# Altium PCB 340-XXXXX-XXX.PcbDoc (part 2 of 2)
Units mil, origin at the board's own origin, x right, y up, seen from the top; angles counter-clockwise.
Board outline 2825 x 4480 mil, 2 copper layers (Top Layer, Bottom Layer), stack 60.8 mil thick; 87 components, 73 nets, 344 pads, 146 vias.
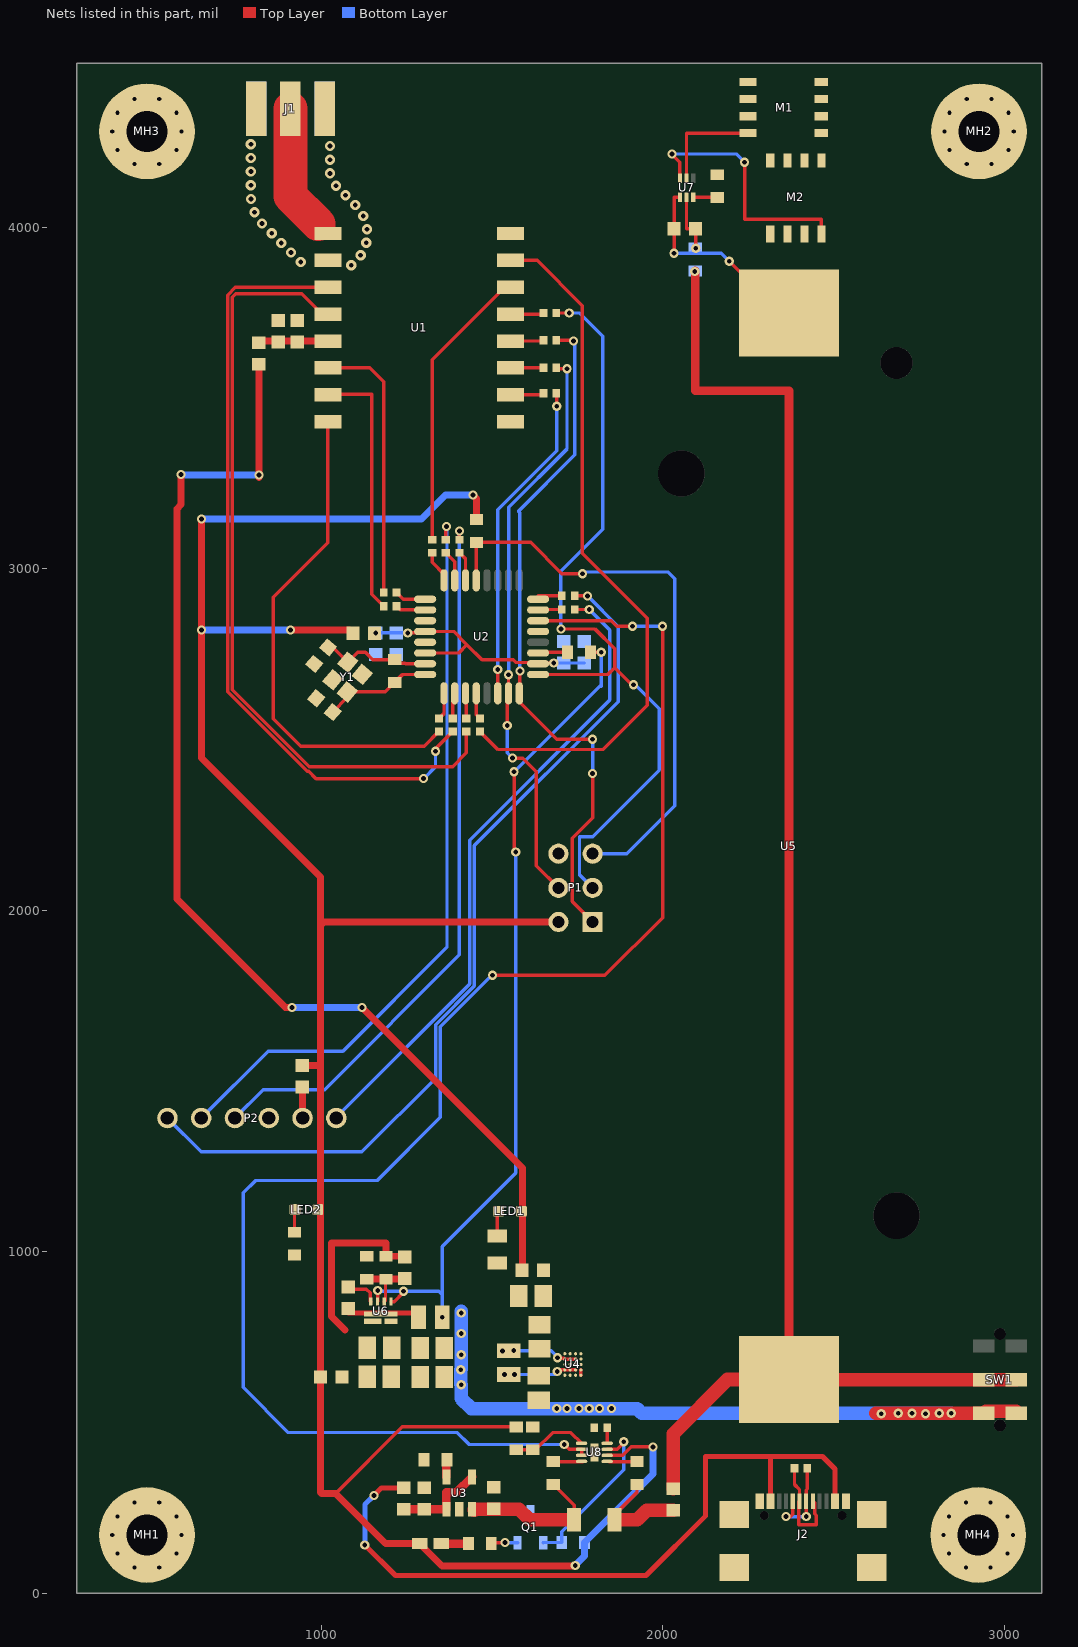
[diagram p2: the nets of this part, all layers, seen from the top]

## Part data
C1 C3 C4 C5: library part 060-00124-000, "CAP, CER, SMT, 25V, +/- 10%, X7R, 0603", DIELECTRIC=X7R, Manufacturer="Kemet Corporation", Manufacturer P/N=C0603C104K3RAC, Package=C0603, TOLERANCE=10%, Value (nF)=100, Value (pF)=100000, Value (µF)=0.1, Voltage=25V
C2 C3 C8 C9: library part 060-00192-001, "CAP, CER, SMT, 1.0UF, 25V, 10%, X5R, 0603", DIELECTRIC=X5R, Manufacturer="Kemet Corporation", Manufacturer P/N=C0603C105K3PAC, Package=C0603, TOLERANCE=10%, Value (nF)=1000, Value (pF)=1000000, Value (µF)=1, Voltage=25V
C6 C7: library part 060-00139-005, "CAP, CER, 10%, 50V, 27PF, CAP0603", DIELECTRIC=NP0, Manufacturer="Kemet Corporation", Manufacturer P/N=C0603C270K5GAC, Package=C0603, TOLERANCE=10%, Value (nF)=0.027, Value (pF)=27, Value (µF)=0.000027, Voltage=50V
C10 C11 C17 C18: library part 060-00196-000, "CAP, CER, 10UF, 16V, X5R, 0805", DIELECTRIC=X5R, Manufacturer="Murata Manufacturing Co., Ltd.", Manufacturer P/N=GRM21BR61C106KE15L, Package=C0805, TOLERANCE=10%, Value (nF)=10000, Value (pF)=10000000, Value (µF)=10, Voltage=16V
C12: library part 060-00269-000, "CAP, CER, 0805, 20%, 6.3V, X5R, 47UF", DIELECTRIC=X5R, Manufacturer="Kemet Corporation", Manufacturer P/N=C0805C476M9PACTU, Package=C0805, TOLERANCE=20%, Value (nF)=47000, Value (pF)=47000000, Value (µF)=47, Voltage=6.3V
C13: library part 060-00243-000, "CAP, CER, 5%, 25V, C0G, 0603, 10,000PF", DIELECTRIC=NP0, Manufacturer="TDK Corporation", Manufacturer P/N=C1608C0G1E103JT, Package=C0603, TOLERANCE=5%, Value (nF)=10, Value (pF)=10000, Value (µF)=0.01, Voltage=25V
C14 C15: library part 060-00268-000, "CAP, CER, 0805, 20%, 10V, X7R, 22UF", DIELECTRIC=X7R, Manufacturer="Taiyo Yuden USA, Inc.", Manufacturer P/N=LMK212BJ226MG-T, Package=C0805, TOLERANCE=20%, Value (nF)=22000, Value (pF)=22000000, Value (µF)=22, Voltage=10V
C16: library part 064-00028-016, "CAP RF, HIQ, NPO, +/-1%, 10GHZ, 200, 100V, 0603, 10PF, ROHS", DIELECTRIC=NP0, Manufacturer=Vishay, Manufacturer P/N=VJ0603D100FXBA, Package=C0603, TOLERANCE=1%, Value (nF)=0.01, Value (pF)=10, Value (µF)=0.00001, Voltage=100V
C19: library part 060-00041-000, "CAP, CER, SMT, 25V, +80/-20%,Y5V,0603,.1uf", DIELECTRIC=Y5V, Manufacturer="Kemet Corporation", Manufacturer P/N=C0603C104M3VAC, Package=C0603, TOLERANCE=20%, Value (nF)=100, Value (pF)=100000, Value (µF)=0.1, Voltage=25V
D1: library part 023-00316-000, "DIODE, LED, RED, SMT, 2.5V, 0603", Current=20mA, LED_COLOR=RED, Manufacturer=Kingbright, Package=D0603, Voltage=2.5V
FB1 FB2 FB3 FB4 FB5 FB6 FB7: library part 082-00014-004, "FERRITE,100MHZ,0603,25%,120OHM ROHS", Current=2A, Manufacturer=Murata, Package=L0603
J1: library part 030-00761-000, "CONN, SMA JACK, FEMALE, EDGE", Manufacturer=LINX, Package=SMA
J2: library part USB4110-GF-A, "CONN USB 2.0 TYPE-C R/A SMT", Manufacturer=GCT
L1 L2: library part 080-00223-000, "INDUCTOR POWER 1UH 1.5A SMD", Current=3.1A, Current_Sat=3.5A, Manufacturer="Vishay Dale", Manufacturer P/N=IHHP0806AZER1R0M01, Package="0.079\" L x 0.063\" W", TOLERANCE=20%
LED1 LED2: library part LED_SMD_Green_0603_570nm, "LED 0603 SMD Green 570nm 50mcd 20mA", Current - Test=20mA, Manufacturer 1="Kingbright Company LLC", Manufacturer Part Number 1=APT1608CGCK, Package / Case="0603 (1608 metric)", Ratings="20mcd min; 50 mcd typ; 570 nm", Supplier Part Number 1=754-1116-1-ND, Voltage - Forward (Vf) @ 10mA=2.0V, Voltage - Forward (Vf) Typ=2.1V
M1 M2: library part FDMS7692, "MOSFET N-CH 30V 14A POWER56", Manufacturer="ON Semiconductor"
MH1 MH2 MH3 MH4: library part MHOLE-120-280, "Mounting Hole"
P1: "Header, 3-Pin, Dual row"
P2: "HC-05 BLUETOOTH MODULE"
Q1: library part 025-00001-000, "TRANS,BJT,PNP,3906,SOT-23", Current=200mA, Manufacturer="Fairchild Semiconductor", Package=SOT-23, Voltage=40V
R1 R24: library part 070-00486-037, "RES, THICK FILM CHIP, SMT, 1/10W, 1%, 0603, 100K OHM", Manufacturer="Panasonic Electronic Devices, Corp.", Manufacturer P/N=ERJ3EKF1003V, Package=R0603, TOLERANCE=1%
R2 R3 R5 R6 R7 R8 R9 R10 R11 R12 R13 R14 R15 R16 R17 R27 R32: library part 070-00475-085_SHORT, "RES, THICK FILM CHIP, 1/16W, 1%, RES0402, 0 OHM, ROHS, SHORT-IN-PAD!", Manufacturer="Vishay-Dale Intertechnology, Inc", Manufacturer P/N=CRCW04020000Z0ED, Package=R0402, TOLERANCE=1%
R4 R29: library part 070-00470-014, "RES, THICK FILM CHIP, SMT, 1/10W, 5%, 0603, 10K OHM", Manufacturer="Vishay-Dale Intertechnology, Inc", Manufacturer P/N=CRCW060310K0JNEA, Package=R0603, TOLERANCE=5%
R18: library part 070-00305-000, "RES, 1/10W, 5%, 0603, I MEG", Manufacturer="KOA-Speer Electronics, Inc.", Manufacturer P/N=RM73B1JT105J, Package=R0603, TOLERANCE=5%
R19: library part 070-00072-000, "RES, 1/8W, 5%, 0805, 330 OHM", Manufacturer="KOA-Speer Electronics, Inc.", Manufacturer P/N=RM73B2AT331J, Package=R0805, TOLERANCE=5%
R20 R25: library part 070-00470-011, "RES, THICK FILM CHIP, SMT, 1/10W, 5%, 0603, 510 OHM", Manufacturer="Panasonic Electronic Devices, Corp.", Manufacturer P/N=ERJ3GEYJ511V, Package=R0603, TOLERANCE=5%
R21: library part 070-00442-000, "RES, 1/16 W, 1%, 0603, 330 OHM", Manufacturer="Panasonic Electronic Devices, Corp.", Manufacturer P/N=ERJ-3ENF3300V, Package=R0603, TOLERANCE=1%
R22: library part 070-00486-071, "RES, THICK FILM CHIP, SMT, 1/10W, 1%, 0603, 316K OHM", Manufacturer="Panasonic Electronic Devices, Corp.", Manufacturer P/N=ERJ3EKF3163V, Package=R0603, TOLERANCE=1%
R23: library part 070-00208-000, "RES, 1/10W, 5%, 0603, 2.2K OHM", Manufacturer="KOA-Speer Electronics, Inc.", Manufacturer P/N=RM73B1JT222J, Package=R0603, TOLERANCE=5%
R26: library part 070-00415-000, "RES, 1/16W, 1%, 0603, 2.00K OHM", Manufacturer="Panasonic Electronic Devices, Corp.", Manufacturer P/N=ERJ-3EKF2001V, Package=R0603, TOLERANCE=1%
R28 R31: library part 070-00486-069, "RES, THICK FILM CHIP, SMT, 1/10W, 1%, 0603, 5.1 OHM", Manufacturer="Panasonic Electronic Devices, Corp.", Manufacturer P/N=ERJ-3EKF5R1V, Package=R0603, TOLERANCE=1%
R30: library part 070-00499-001, "RES, THICK FILM, CURRENT SENSE, 1/2 W, 1%, RES1206, 0.05 OHMS", Manufacturer="TT Electronics, PLC", Manufacturer P/N=LRC-LR1206LF-01-R050-F, Package=R1206, TOLERANCE=1%
R33: library part 070-00113-000, "RES,1/10W,1%,0603,100K OHM", Manufacturer="Panasonic Electronic Devices, Corp.", Manufacturer P/N=ERJ-3EKF1003V, Package=R0603, TOLERANCE=1%
R34: library part 070-00597-000, "RES, METAL FILM, 1/16W, .5%, 0603, SMD, 4.02K", Manufacturer=Susumu, Manufacturer P/N=RR0816P-4021-D-59H, Package=R0603, TOLERANCE=1%
SW1: library part JS202011JAQN, "SWITCH SLIDE DPDT 300MA 6V", Manufacturer P/N=C&K
U1: library part "LoRa Module", "RFM69HCW WIRELESS TRANSCEIVER 91", Current=130mA, Manufacturer=SparkFun, Manufacturer P/N=COM-13909, Package=Module, Voltage-Input="1.8V ~ 3.6V"
U2: "8-bit AVR Microcontroller, 32KB Flash, 1KB EEPROM, 2KB SRAM, 32-pin TQFP, Industrial Grade (-40°C to 85°C)", Supplier Part Number 1=ATMEGA328P-AUR-ND
U3: "IC LI-ION/LI-POLY CTRLR SOT23-5", Current=500mA, Manufacturer="Microchip Technology", Manufacturer P/N=MCP73812T-420I/OT, Package="SC-74A, SOT-753", Voltage-Input="3.75V ~ 6V"
U4: Manufacturer Name="Texas Instruments"
U5: library part 1042, "HOLDER BATTERY 1CELL 18650 SMD", Manufacturer="Keystone Electronics"
U6: library part TPS61230ARNSR, "TPS61230ARNSR", Manufacturer Name="Texas Instruments"
U7: "IC LITHIUM BATT PROTECT 6-SON", Manufacturer="Texas instruments"
U8: library part INA381A3IDSGR, "LOW COST CURRENT SENSOR WITH COM", Manufacturer=TI, Package="8-WFDFN Exposed Pad", Voltage-Input="0V ~ 6V"
Y1: library part FA-20H, "CRYSTAL 16.0000MHZ 8PF SMD", Frequency Stability="10 ppm", Manufacture=EPSON, Manufacture PN="FA-20H 16.0000MF10Z-AJ0", Package="0.098\" L x 0.079\" W (2.50mm x 2.00mm)", Voltage="2.7V - 3.6V"

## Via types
v1: diameter 27, hole 14, Top Layer to Bottom Layer, 124 vias
v2: diameter 30, hole 14, Top Layer to Bottom Layer, 22 vias

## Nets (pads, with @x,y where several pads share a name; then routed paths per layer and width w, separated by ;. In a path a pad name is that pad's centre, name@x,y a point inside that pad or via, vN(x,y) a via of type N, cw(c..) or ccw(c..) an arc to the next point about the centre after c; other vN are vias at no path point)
3.3V: FB2.2 FB6.2 LED1.A | length 3446.1
  Top Layer w20: v1(590,3275) 590,3187.53 577.5,3175.03 577.5,2032.5 895,1715 v1(915,1715) ; v1@817.72,3266.93 v1(817.72,3273.94) FB2.2@817.72,3598.5 ; v1(1120,1715) 1590,1245 FB6.2@1590,945
  Bottom Layer w20: v1(590,3275) 591.06,3273.94 v1(817.72,3273.94) ; v1(915,1715) v1(1120,1715)
5V: D1.A FB1.1 FB3.1 FB7.2 LED2.A P1.2 R4.1 R29.1 R33.1 U8.2 | length 7121.2
  Top Layer w10: 998.01,1544.5 998.5,1544 ; 1042.5,291.5 1237.47,486.46 R33.1@1571,486.46 ; U8.2@1837.4,403.14 1883.14,403.14 1908,428 v1(1972,428)
  Top Layer w20: v1(650,3145) v1(650,2820) 650,2445 998.5,2096.5 998.5,1955 ; v1(910,2820) 1083.5,2820 FB1.1@1093.5,2810 ; FB3.1@945,1544.5 998.01,1544.5 ; v1(1445,3215) 1455,3205 R4.1@1455,3150 ; P1.2@1695,1965 1008.5,1965 998.5,1955 ; v1(1744,81) 1742,79 1354.5,79 D1.A@1288.5,145 1189,145 1042.5,291.5 1001.5,291.5 998.5,294.5 FB7.2@998.5,632.68 998.5,1544 998.5,1955
  Bottom Layer w20: v1(650,2820) v1(910,2820) ; v1(650,3145) 1294.21,3145 1364.21,3215 v1(1445,3215) ; v1(1744,81) 1771.46,108.46 R29.1@1771.46,148 1972,348.54 v1(1972,428)
BT_EN: P2.1 R2.1 | length 1887.6
  Top Layer w10: R2.1@1742.8,2880 v1(1785,2880)
  Bottom Layer w10: P2.1@1044.49,1391 1044.49,1392.91 1435,1783.42 1435,2205 1845,2615 1845,2820 v1(1785,2880)
BT_RX: P2.5 R10.1 | length 2199.1
  Top Layer w10: R10.1@1365,3083.9 v1@1365,3122.76
  Bottom Layer w10: P2.5@648.82,1391 844.82,1587 1064,1587 1368.46,1891.46 1368.46,1932.46 1368.46,3109.02 v1@1368.46,3124.76
  other v1: 1367,3122.76
BT_STATE: P2.6 R3.1 | length 2623.6
  Top Layer w10: R3.1@1742.8,2920 v1(1780,2920)
  Bottom Layer w10: P2.6@550,1391 649,1292 1119,1292 1335.06,1508.06 1335.06,1663.77 1448.94,1777.65 1448.94,2188.94 1870,2610 1870,2830 v1(1780,2920)
BT_TX: P2.4 R9.1 | length 2122.5
  Top Layer w10: R9.1@1405,3083.9 v1(1405,3110)
  Bottom Layer w10: P2.4@747.64,1391 830.64,1474 1010,1474 1405,1869 v1(1405,3110)
BT_VCC: FB3.2 P2.2 | length 90.8
  Top Layer w10: P2.2@945,1391.67 P2.2@945.67,1391
  Top Layer w20: P2.2@945,1391.67 FB3.2@945,1481.5
Charge_Sense: U2.22 U8.6 U8.7 | length 4594.8
  Top Layer w10: v1(1502,1809) 1831,1809 2000,1978 v1(2000,2831) ; U2.22@1635.35,2847.24 1849.76,2847.24 1866,2831 v1(1912,2831) ; v1(1712,435) 1726.14,420.86 U8.6@1762.6,420.86 U8.7@1762.6,403.14
  Bottom Layer w10: v1(1502,1809) 1500,1807 1498,1807 1349,1658 1349,1393 1164,1208 808,1208 772,1172 772,602 904,470 1399,470 1434,435 v1(1712,435) ; v1(1912,2831) v1(2000,2831)
DSP_CS: R5.1 U2.14 | length 950.7
  Top Layer w10: v1(1517,2704) 1517,2634.89 U2.14@1517.24,2634.65 ; R5.1@1688.9,3513.19 1690,3512.13 v1(1690,3475)
  Bottom Layer w10: v1(1517,2704) 1517,3172 1690,3345 v1(1690,3475)
DSP_MISO: P1.1 R7.1 U2.16 | length 2026.3
  Top Layer w10: v1(1582,2700) 1582,2640.88 1578,2636.88 U2.16@1580.24,2634.65 1580.24,2609.76 1690,2500 v1(1795,2500) ; R7.1@1688.9,3668.19 1736.81,3668.19 v1(1738.94,3666.06) ; P1.1@1795,1965 1735,2025 1735,2210 1795,2270 v1(1795,2400)
  Bottom Layer w10: v1(1582,2700) 1582,3164 1578,3168 1742.94,3332.94 1742.94,3662.06 v1(1738.94,3666.06) ; v1(1795,2400) v1(1795,2500)
DSP_MOSI: P1.4 R6.1 U2.15 | length 1712
  Top Layer w10: v1(1545,2540) 1545,2630.91 U2.15@1548.74,2634.65 v1@1548.74,2696.58 ; v1(1560,2445) 1590,2445 1630,2405 1630,2130 P1.4@1695,2065 ; R6.1@1688.9,3588.19 1692.13,3585 v1(1720,3585)
  Bottom Layer w10: v1(1545,2540) 1545,2460 v1(1560,2445) ; v1(1549,2689) 1549,3179 1720,3350 v1(1720,3585)
DSP_RESET: P1.5 R4.2 U2.29 | length 1702.8
  Top Layer w10: U2.29@1454.25,2965.35 1454.25,3075.79 R4.2@1455,3076.54 1613.46,3076.54 1705,2985 v1(1765,2985)
  Bottom Layer w10: v1(1765,2985) 1770,2990 2015,2990 2035,2970 2035,2305 1895,2165 P1.5@1795,2165
DSP_SCK: P1.3 R8.1 U2.17 | length 2383.9
  Top Layer w10: U2.17@1635.35,2689.76 1839.76,2689.76 1860,2710 ; R8.1@1688.9,3748.19 v1(1726.81,3748.19) ; v1(1702,2823) 1802,2823 1860,2765 1860,2710 ; v1(1915,2660) 1910,2660 1860,2710
  Bottom Layer w10: v1(1702,2823) 1702,2988 1700,2990 1825,3115 1825,3680 1756.81,3748.19 v1(1726.81,3748.19) ; P1.3@1795,2065 1756.54,2103.46 1756.54,2215 1795,2215 1990,2410 1990,2590 1920,2660 v1(1915,2660)
GND: C1.2 C2.2 C3.2 C4.2 C5.2 C6.1 C7.1 C8.2 C9.2 C10.2 C11.2 C12.2 C14.2 C15.2 C17.2 C18.2 J1.2 J2.A1 J2.A12 J2.H1 J2.H2 J2.H3 J2.H4 M1.1 M1.2 M1.3 MH1.1 MH2.1 MH3.1 MH4.1 P1.6 P2.3 Q1.3 R19.2 R23.2 R24.2 R25.2 R26.2 R32.1 R34.2 U1.1 U1.8 U1.10 U2.3 U2.5 U2.21 U3.2 U4.8 U4.9 U4.10 U4.11 U4.12 U6.6 U8.9 Y1.2 Y1.4
  other v2: 1088.02,3888.36 940.22,3897.28 1115.7,3917.24 911.72,3925.34 883.43,3953.63 1131.87,3953.83 855.15,3981.91 1134.22,3993.76 826.99,4010.32 1123.16,4032.19 804.73,4043.56 1099.78,4064.66 794.81,4082.31 1071.5,4092.94 1043.21,4121.22 794.25,4122.3 1025.75,4157.21 794.25,4162.3 1025.75,4197.21 794.25,4202.3 1025.75,4237.21 794.25,4242.3
LORA_DIO0: R12.1 U1.14 | length 797.2
  Top Layer w10: U1.14@1019.57,3587.48 1142.52,3587.48 1182.91,3547.09 R12.1@1182.91,2930
LORA_DIO1: R13.1 U1.15 | length 764.2
  Top Layer w10: U1.15@1019.57,3508.74 1021.42,3510.59 1147.99,3510.59 1147.99,2924.92 R13.1@1182.91,2890
LORA_DIO2: R14.1 U1.16 | length 1472
  Top Layer w10: U1.16@1019.57,3430 1019.57,3075.08 860,2915.51 860,2560 940,2480 1302.13,2480 R14.1@1345,2522.91
LORA_DIO3: R15.1 U1.11 | length 2316.9
  Top Layer w10: U1.11@1019.57,3823.7 748.99,3823.7 726.06,3800.77 726.06,2639.23 959.23,2406.06 963.94,2406.06 985,2385 v1(1300,2385) ; v1(1335,2465) 1335,2472.87 R15.1@1385,2522.91
  Bottom Layer w10: v1(1300,2385) 1335,2420 v1(1335,2465)
LORA_DIO4: R16.1 U1.12 | length 2316.2
  Top Layer w10: U1.12@1019.57,3744.96 1003.04,3744.96 943,3805 750,3805 740,3795 740,2645 965,2420 1385,2420 1425,2460 R16.1@1425,2522.91
LORA_DIO5: R17.1 U1.7 | length 2079.3
  Top Layer w10: R17.1@1465,2522.91 1517.87,2470 1825,2470 1955,2600 1955,2855 1765,3045 1765,3770 1632.56,3902.44 U1.7@1555,3902.44
LORA_RESET: R11.1 U1.6 | length 845.2
  Top Layer w10: R11.1@1325,3083.9 1325,3611 1537.7,3823.7 U1.6@1555,3823.7
NetC1_1: C1.1 C2.1 FB2.1 U1.13 | length 205.7
  Top Layer w20: FB2.1@815,3663.5 817.72,3666.22 U1.13@1019.57,3666.22
NetC3_1: C3.1 C4.1 C5.1 FB1.2 U2.4 U2.6 U2.18 | length 784.2
  Top Layer w10: v1(1253.5,2811.5) 1300.39,2811.5 U2.4@1304.65,2815.75 1388.25,2815.75 1427,2777 ; U2.6@1304.65,2752.76 1402.76,2752.76 1427,2777 ; v1(1681.5,2723.5) 1637.6,2723.5 U2.18@1635.35,2721.26 1631.61,2725 1570.14,2725 1562.14,2733 1471,2733 1427,2777
  Bottom Layer w10: v1(1160,2811.5) C3.1@1220,2811.5 v1(1253.5,2811.5) ; v1(1681.5,2723.5) C5.1@1710,2723.5 C3.1@1770,2723.5
NetC6_2: C6.2 R18.1 U2.7 Y1.1 | length 342.6
  Top Layer w10: C6.2@1020.25,2769.13 1034.08,2769.13 Y1.1@1077.78,2725.43 ; Y1.1@1063.94,2725.43 Y1.1@1077.78,2725.43 ; U2.7@1304.65,2721.26 1246.97,2721.26 1245.23,2723 1225.46,2723 R18.1@1215,2733.46 1151.54,2733.46 1130,2755 1107.35,2755 Y1.1@1077.78,2725.43
NetC7_2: C7.2 R18.2 U2.8 Y1.3 | length 325.5
  Top Layer w10: C7.2@1034.13,2579.75 1076.98,2622.61 Y1.3@1076.98,2638.73 1187.19,2638.73 R18.2@1215,2666.54 1238.23,2689.76 U2.8@1304.65,2689.76
NetC8_1: C8.1 FB4.1 U3.1 U3.4 | length 268.3
  Top Layer w25: FB4.1@1241.77,245.12 1242.28,245.63 U3.1@1366.97,245.63 1366.97,295 1396.65,295 U3.4@1441.77,340.12
NetC9_1: C9.1 R30.2 R31.1 U3.3 | length 457.3
  Top Layer w10: 1674.02,215 1680,220.98 1680,215.98 ; R31.1@1680,318.07 1740.94,257.13 R30.2@1740.94,215
  Top Layer w25: U3.3@1443.27,247.13 U3.3@1448,242.39
  Top Layer w40: U3.3@1448,242.39 1448,245.63 1579.37,245.63 1610,215 1674.02,215 R30.2@1740.94,215
NetC11_1: C11.1 C12.1 FB6.1 U4.1 U4.2 U4.3 U4.4
NetC13_1: C13.1 U6.1 | length 94.7
  Top Layer w10: C13.1@1080,890 1132.39,890 1143.56,878.82 1143.56,855.02 U6.1@1145.47,853.11
NetC13_2: C13.2 L2.2 U6.5 | length 217.5
  Top Layer w10: L2.2@1285.16,807.68 L2.2@1285.16,820
  Top Layer w15: C13.2@1080,820 L2.2@1285.16,820
NetC14_1: C14.1 C15.1 C16.1 FB7.1 R22.1 U6.7 | length 527.4
  Top Layer w20: 1070,770 1030,810 1030,1025 1190,1025 R22.1@1190,986.14 1245,986.14 C16.1@1245,984.17
NetC16_2: C16.2 R22.2 R24.1 U6.3 | length 238.5
  Top Layer w10: U6.3@1184.84,853.11 1188.44,856.7 1188.44,915.62 1184.84,919.21 R22.2@1190,919.21
  Top Layer w20: C16.2@1245,921.18 1243.03,919.21 R22.2@1184.84,919.21 ; R22.2@1184.84,919.21 R24.1@1133.19,919.21 R22.2@1184.84,919.21
NetC19_1: C19.1 R21.2 U7.5 | length 176.2
  Top Layer w10: U7.5@2070,4086.65 2070,3995 C19.1@2096.5,3995 2096.5,3938.46 v1@2095,3938.46
  other v1: 2097,3938
NetC19_2: C19.2 M2.1 M2.2 M2.3 U5.2 U7.4 | length 588.9
  Top Layer w10: v1(2033.5,3923.5) C19.2@2033.5,3995 2033.5,4086.65 U7.4@2050.31,4086.65 ; v1(2195,3900) 2346.3,3748.7 U5.2@2370.04,3748.7
  Bottom Layer w10: v1(2033.5,3923.5) 2171.5,3923.5 v1(2195,3900)
NetD1_C: D1.C R20.1 | length 80
  Top Layer w25: D1.C@1351.5,145 R20.1@1431.54,145
NetFB5_1: FB5.1 R28.1 R30.1 | length 320
  Top Layer w10: R30.1@1859.06,215 1859.06,229.06 1925,295 R28.1@1925,318.07 R28.1@1925,323.07 ; 1925,215.98 1925.98,215
  Top Layer w40: R30.1@1859.06,215 1925.98,215 1953.11,242.13 FB5.1@2031.02,242.13
NetJ1_1: J1.1 U1.9 | length 370.7
  Top Layer w100: J1.1@910,4346.42 910,4090.75 991.37,4009.37
NetJ2_A6: J2.A6 J2.B6 R27.2 | length 295.9
  Top Layer w10: R27.2@2386.1,365 2386.1,317.9 2400.68,303.31 J2.A6@2400.68,269.32 2398.44,267.07 2398.44,200.56 2450,200.56 2450,227 2444.9,232.1 2444.9,264.48 J2.B6@2440.06,269.32
NetJ2_A7: J2.A7 J2.B7 R27.1 | length 268
  Top Layer w10: v1(2361,224) 2374,224 2381,231 J2.B7@2381,269.32 ; v1(2420.87,224.29) 2420.87,225.13 2418,228 2420.37,230.37 J2.A7@2420.37,269.32 2420.37,301.37 2423.9,304.9 R27.1@2423.9,365
  Bottom Layer w10: v1(2361,224) 2414,224 2417,227 2420,224 2420.29,224.29 v1(2420.87,224.29)
NetL1_1: L1.1 U4.13 U4.14 U4.15 | length 221.9
  Top Layer w10: v1(1691.68,649.11) 1691.97,649.11 1693.79,647.29 1700,653.5 U4.13@1713.5,653.5 U4.15@1745,653.5
  Bottom Layer w10: v1(1537,640) 1537,638.16 1535.16,640 v1(1566,640) 1683.5,640 1691.68,648.17 v1(1691.68,649.11)
NetL1_2: L1.2 U4.5 U4.6 U4.7 | length 222.8
  Top Layer w10: v1(1692,689) 1693.72,687.28 1711.22,687.28 U4.5@1713.5,685 U4.7@1745,685
  Bottom Layer w10: v1@1535,709.84 1535.16,710 1535.32,709.84 v1(1564,709.84) 1673.35,709.84 1673.5,710 1693,690.5 1692,689.5 v1(1692,689)
  other v1: 1531,709
NetLED1_K: LED1.K R19.1 | length 76.2
  Top Layer w10: R19.1@1516,1045.37 1516,1118 LED1.K@1519.54,1118
NetLED2_K: LED2.K R25.1 | length 63.1
  Top Layer w10: R25.1@922,1056.46 922,1118 LED2.K@923.54,1118
NetM1_4: M1.4 U7.2 | length 311.5
  Top Layer w10: U7.2@2070,4143.35 2070,4275.2 M1.4@2249.68,4275.2
NetM1_D: M1.D M2.D
NetM2_4: M2.4 U7.3 | length 738.1
  Top Layer w10: v1(2027.16,4214) 2027.16,4213 2050.16,4190 U7.3@2050.16,4143.35 ; v1(2240,4190) 2240,4023.06 2464.8,4023.06 M2.4@2464.8,3979.68
  Bottom Layer w10: v1(2027.16,4214) 2216,4214 v1(2240,4190)
NetQ1_1: Q1.1 R29.2 U8.3 | length 483.9
  Top Layer w10: U8.3@1837.4,420.86 1866.86,420.86 1886,440 v1(1886,443)
  Bottom Layer w10: Q1.1@1650.4,147.72 1650.68,148 R29.2@1704.54,148 1704.54,179.54 1886,361 v1(1886,443)
NetQ1_2: Q1.2 R20.2 | length 78.3
  Top Layer w10: R20.2@1498.46,145 1501.19,147.72 v1(1538.72,147.72)
  Bottom Layer w10: v1(1538.72,147.72) Q1.2@1575.6,147.72
NetR1_2: R1.2 U2.19 | length 88.7
  Top Layer w10: U2.19@1635.35,2752.76 1635.35,2755 R1.2@1721.81,2755
NetR2_2: R2.2 U2.23 | length 70.9
  Top Layer w10: U2.23@1635.35,2878.74 1635.35,2880 R2.2@1705,2880
NetR3_2: R3.2 U2.24 | length 79.4
  Top Layer w10: U2.24@1635.35,2910.24 1635.35,2920 R3.2@1705,2920
NetR5_2: R5.2 U1.2 | length 97.9
  Top Layer w10: U1.2@1555,3508.74 1646.62,3508.74 R5.2@1651.1,3513.19
NetR6_2: R6.2 U1.3 | length 96.4
  Top Layer w10: U1.3@1555,3587.48 1650.35,3587.48 R6.2@1651.1,3588.19
NetR7_2: R7.2 U1.4 | length 96.9
  Top Layer w10: U1.4@1555,3666.22 1649.09,3666.22 R7.2@1651.1,3668.19
NetR8_2: R8.2 U1.5 | length 97.4
  Top Layer w10: U1.5@1555,3744.96 1647.83,3744.96 R8.2@1651.1,3748.19
NetR9_2: R9.2 U2.30 | length 88.1
  Top Layer w10: R9.2@1405,3046.1 1422.76,3028.31 U2.30@1422.76,2965.35
NetR10_2: R10.2 U2.31 | length 91.6
  Top Layer w10: R10.2@1365,3046.1 1391.26,3019.8 U2.31@1391.26,2965.35
NetR11_2: R11.2 U2.32 | length 95.1
  Top Layer w10: R11.2@1325,3046.1 1325,3018.62 1359.76,2983.86 U2.32@1359.76,2965.35
NetR12_2: R12.2 U2.1 | length 92.1
  Top Layer w10: R12.2@1220.71,2930 1240.51,2910.24 U2.1@1304.65,2910.24
NetR13_2: R13.2 U2.2 | length 88.6
  Top Layer w10: R13.2@1220.71,2890 1232.01,2878.74 U2.2@1304.65,2878.74
NetR14_2: R14.2 U2.9 | length 80
  Top Layer w10: R14.2@1345,2560.71 1359.76,2575.51 U2.9@1359.76,2634.65
NetR15_2: R15.2 U2.10 | length 76.5
  Top Layer w10: R15.2@1385,2560.71 1385,2628.39 U2.10@1391.26,2634.65
NetR16_2: R16.2 U2.11 | length 74.9
  Top Layer w10: U2.11@1422.76,2634.65 1425,2632.4 R16.2@1425,2560.71
NetR17_2: R17.2 U2.12 | length 78.3
  Top Layer w10: U2.12@1454.25,2634.65 1454.25,2571.5 R17.2@1465,2560.71
NetR23_1: R23.1 U7.6 | length 74.4
  Top Layer w10: U7.6@2089.69,4086.65 2150.12,4086.65 R23.1@2160,4096.54
NetR26_1: R26.1 U3.5 | length 50.5
  Top Layer w15: R26.1@1366.97,388.5 R26.1@1368.46,390
  Top Layer w25: U3.5@1366.97,340.12 R26.1@1366.97,388.5
NetR28_2: R28.2 U8.1 | length 81
  Top Layer w10: U8.1@1843.98,385 R28.2@1925,385
NetR31_2: R31.2 U8.8 | length 86
  Top Layer w10: R31.2@1680,385 U8.8@1766.02,385
NetR32_2: R32.2 U8.4 | length 45.4
  Top Layer w10: U8.4@1837.4,438.57 U8.4@1837.4,438.57 R32.2@1837.4,484
NetR33_2: R33.2 R34.1 U8.5 | length 225.5
  Top Layer w10: R33.2@1571,419.54 1627.54,419.54 1678,470 1731.17,470 U8.5@1762.6,438.57
VBAT: C10.1 C17.1 C18.1 L2.1 R1.1 SW1.1 U4.16 U4.17 U4.18 U4.19 U4.20 U6.2 U6.4 | length 4612.9
  Top Layer w10: U6.2@1165.16,853.11 1166,853.95 v1(1166,886) ; U6.4@1204.53,853.11 1214.11,853.11 1241,880 v1(1241,884) ; v1(1565,2405) 1565,2175 v1(1570,2170) ; U4.20@1760.75,637.76 U4.16@1760.75,653.5 ; R1.1@1788.74,2755 v1(1820,2755)
  Top Layer w40: 2625,526.57 v1(2690,526.57) v1(2730,526.57) v1(2810,526.57) v1(2845,526.57) SW1.1@2940.51,526.57 2946.73,532.8 3035,532.8 SW1.1@3035,526.57
  Bottom Layer w10: v1@1158.02,883 v1@1166,883 ; v1(1166,886) v1@1166,883 ; v1(1354.84,807.68) 1354.84,874.17 ; v1(1565,2405) 1820,2660 ; v1(1570,2170) 1570,1230 1354.84,1014.84 1354.84,874.17 ; 1820,2655 1820,2660 ; v1(1820,2755) 1820,2660 ; v1@1166,883 1167,884 v1(1241,884) 1345.02,884 1354.84,874.17
  Bottom Layer w40: v1@1410,825 v1(1410,820) v1(1410,760) v1(1410,697.5) 1410,655 v1(1409,654) 1409,611 v1(1410,610) 1410,570 1440,540 v1(1690,540) v1(1720,540) v1(1755,540) v1(1785,540) v1(1815,540) v1(1850,540) 1925,540 1938.43,526.57 v1(2690,526.57) v1(2730,526.57) v1(2810,526.57) v1(2845,526.57)
  other v1: 2640,525 2770,525
VBATs: FB5.2 R21.1 SW1.2 U5.1 | length 4752.3
  Top Layer w25: v1@2095,3871.54 2095,3520 2370.04,3520 U5.1@2370.04,625.08
  Top Layer w40: FB5.2@2031.02,305.12 2031.02,466.02 2190.08,625.08 U5.1@2370.04,625.08 2370.12,625 SW1.2@2940.51,625 SW1.2@3035,625
  other v1: 2094,3870
VUSB: FB4.2 J2.A4 J2.A9 | length 2152.6
  Top Layer w15: v1(1128,141) 1218,51 1951,51 2126,226 2126,400 2316,400 ; v1(1155,286) 1177.11,308.11 FB4.2@1241.77,308.11 ; J2.A4@2315.94,269.32 2315.94,399.94 2316,400 ; J2.A9@2505,269.32 2505,363 2468,400 2316,400
  Bottom Layer w15: v1(1128,141) 1128,259 v1(1155,286)
pads on no net: J2.0 J2.A5 J2.A8 J2.B5 J2.B8 LED1.0 LED2.0 SW1.3 SW1.4 U2.13 U2.20 U2.25 U2.26 U2.27 U2.28 U5.0 U7.1
copper on no net:
  other v1: 2110,66 2698,78 2698,131 2129,138 2212,178 2662,180 2602,181 2178,183 1544,312 1299,349 1803,349 1504,355 2289,367 2536,378 1305,443 1762,495 961,796 1502,804 1442,889 1076,956 948,2576 1151,2597 1643,2635 937,2668 931,2750 1446,2809 1486,2827 1198,2853 1444,2875 1297.6,2952.54 1631,2971 1559,3367 1628,3382 1623,3438 815,3722 868,3774 937,3778 1630,3971 1459,3988 1617,4022 1489,4031 1553,4034 2204,4143 2186,4322 2185,4372 2192,4421

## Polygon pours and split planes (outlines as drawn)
GND on Top Layer (solid, shelved, pour order 18): 282,4486 282,0 3110,0 3110,4480
GND on Top Layer (solid, shelved, pour order 26): 160 vertices, not listed, extent 778.98,3850.33 1150.41,4506.93
NetC11_1 on Top Layer (solid, shelved, pour order 10): 1620,970 1620,750 1695,750 1695,695 1825,695 1825,970
VBAT on Top Layer (solid, shelved, pour order 8): 1605,600 1605,520 1865,520 1865,645 1695,645 1695,600
NetM1_D on Top Layer (solid, shelved, pour order 16): 2307,4427 2485,4427 2485,4037 2307,4037
NetC19_2 on Top Layer (solid, shelved, pour order 12): 2301,4005 2301,3830 2495,3830 2495,4005
no net on Top Layer (solid, shelved, pour order 6): 1695,645
no net on Top Layer (solid, shelved, pour order 4): 1795,645
NetC14_1 on Top Layer (solid, shelved, pour order 2): 1165,805 1165,595 1035,595 1035,805
VBAT on Top Layer (solid, shelved, pour order 0): 1330,845 1330,590 1435,590 1435,845
GND on Bottom Layer (solid, shelved, pour order 20): 288,4483 288,-3 3108,-3 3108,4477

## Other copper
Top Layer:
  pour cut-out: 952.92,4474.86 965.04,4469.84 975.44,4461.86 983.42,4451.45 988.44,4439.34 990.15,4426.34 990.15,4406.61 993.52,4402.21 996.3,4397.41 1000.08,4390.86 1000.08,4390.85 1005.12,4378.69 1008.51,4366.03 1010.23,4352.97 1010.23,4349.68 1010.66,4346.42 1010.66,4132.44 1090.75,4052.36 1092.75,4049.75 1095.08,4047.42 1103.09,4036.97 1105.86,4032.18 1109.65,4025.62 1114.69,4013.46 1118.08,4000.79 1119.8,3987.74 1119.8,3974.62 1118.08,3961.57 1114.69,3948.91 1109.65,3936.74 1107.25,3932.59 1103.09,3925.39 1095.08,3914.94 1085.81,3905.67 1075.36,3897.66 1070.56,3894.89 1064,3891.1 1051.84,3886.06 1039.18,3882.67 1026.12,3880.95 1013.01,3880.95 999.96,3882.67 987.29,3886.06 975.13,3891.1 970.97,3893.5 963.77,3897.66 953.33,3905.67 951,3908 948.39,3910 838.82,4019.57 836.82,4022.18 834.49,4024.51 826.48,4034.95 825.31,4036.97 823.7,4039.75 819.92,4046.31 814.88,4058.47 811.49,4071.14 809.77,4084.19 809.77,4087.48 809.34,4090.75 809.34,4346.42 809.77,4349.68 809.77,4352.97 811.49,4366.03 814.88,4378.69 819.92,4390.85 819.92,4390.86 822.32,4395.01 826.48,4402.21 829.85,4406.61 829.85,4426.34 831.56,4439.34 836.58,4451.45 844.56,4461.86 854.96,4469.84 867.08,4474.86 880.08,4476.57 939.92,4476.57

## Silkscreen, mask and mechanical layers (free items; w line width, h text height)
Top Overlay:
  text "5V" at 892,1241 h60
  text "3.3V" at 1475,1232 h60
  text "ON---OFF" at 3036,864 h60 r90
  text "Charging" at 1172,49 h60
Outline_Mech3:
  lines w10: 270,-5 270,4480 3110,4480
